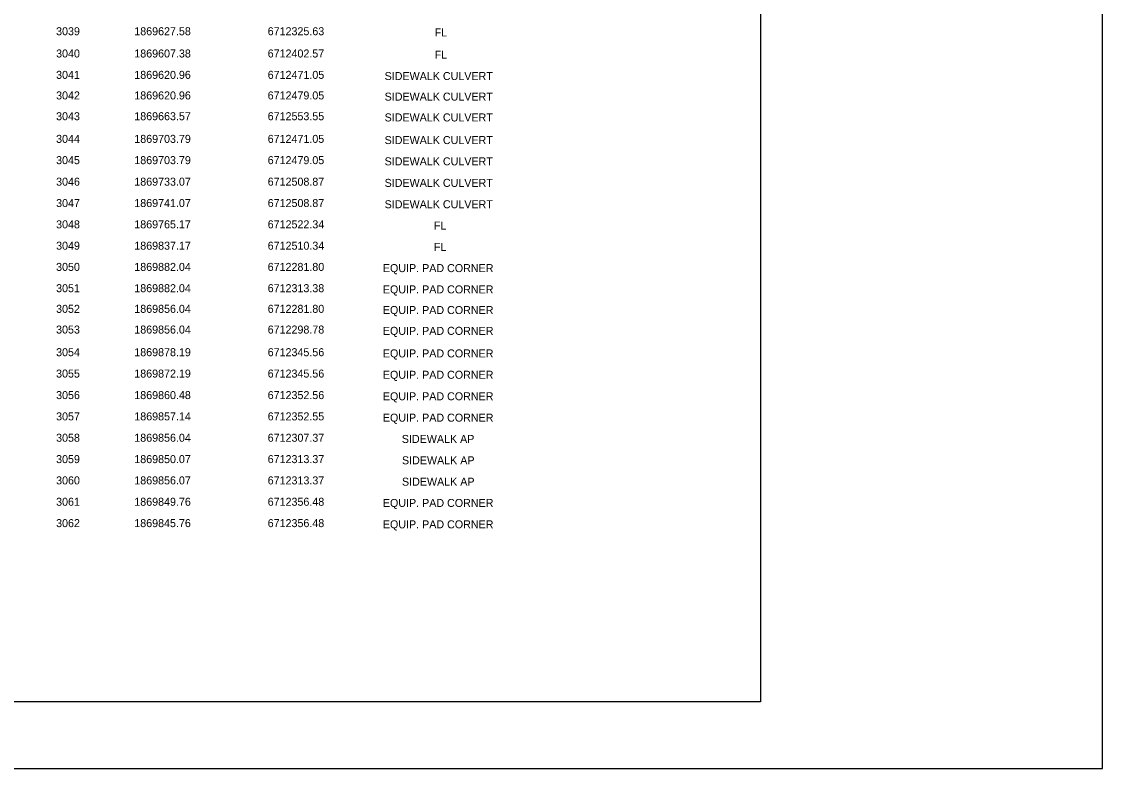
# Model space of a CAD drawing. Extents: x 0 to 4.36, y 0 to 2.5.
# Drawn here: x 2.15 to 3.5, y 0 to 0.933 of the extents above; entities that cross this region are included whole.
import ezdxf

# ---------------------------------------------------------------- set-up
doc = ezdxf.new("R2010")
doc.units = 0
for name, color, linetype in [('C-TEXT', 7, 'Continuous'), ('G-TTLB-OTLN', 7, 'Continuous'), ('G-TTLB-VIEW', 7, 'Continuous')]:
    doc.layers.add(name, color=color, linetype=linetype)

msp = doc.modelspace()

# ---------------------------------------------------------------- linework, layer by layer
at = {"layer": 'G-TTLB-OTLN'}
msp.add_lwpolyline([(0, 0), (3.5, 0), (3.5, 2.5), (0, 2.5)], close=True, dxfattribs=at)
at = {"layer": 'G-TTLB-VIEW'}
msp.add_lwpolyline([(0.1667, 2.4167), (3.0729, 2.4167), (3.0729, 0.0833), (0.1667, 0.0833)], close=True, dxfattribs=at)

# ---------------------------------------------------------------- texts
at = {"layer": 'C-TEXT'}
for s, p in [('3039', (2.1926, 0.9162)), ('1869627.58', (2.2903, 0.9162)), ('6712325.63', (2.457, 0.9162)), ('FL', (2.6656, 0.9147)), ('3040', (2.1926, 0.8884)), ('1869607.38', (2.2903, 0.8884)), ('6712402.57', (2.457, 0.8884)), ('FL', (2.6656, 0.8869)), ('3041', (2.1926, 0.8617)), ('1869620.96', (2.2903, 0.8617)), ('6712471.05', (2.457, 0.8617)), ('SIDEWALK CULVERT', (2.6031, 0.8602)), ('3042', (2.1926, 0.836)), ('1869620.96', (2.2903, 0.836)), ('6712479.05', (2.457, 0.836)), ('SIDEWALK CULVERT', (2.6031, 0.8345)), ('3043', (2.1926, 0.81)), ('1869663.57', (2.2903, 0.81)), ('6712553.55', (2.457, 0.81)), ('SIDEWALK CULVERT', (2.6031, 0.8085)), ('3044', (2.1926, 0.7817)), ('1869703.79', (2.2903, 0.7817)), ('6712471.05', (2.457, 0.7817)), ('SIDEWALK CULVERT', (2.6031, 0.7802)), ('3045', (2.1926, 0.7551)), ('1869703.79', (2.2903, 0.7551)), ('6712479.05', (2.457, 0.7551)), ('SIDEWALK CULVERT', (2.6031, 0.7536)), ('3046', (2.1926, 0.7282)), ('1869733.07', (2.2903, 0.7282)), ('6712508.87', (2.457, 0.7282)), ('SIDEWALK CULVERT', (2.6031, 0.7267)), ('3047', (2.1926, 0.7015)), ('1869741.07', (2.2903, 0.7015)), ('6712508.87', (2.457, 0.7015)), ('SIDEWALK CULVERT', (2.6031, 0.7)), ('3048', (2.1926, 0.6749)), ('1869765.17', (2.2903, 0.6749)), ('6712522.34', (2.457, 0.6749)), ('FL', (2.6647, 0.6733)), ('3049', (2.1926, 0.6482)), ('1869837.17', (2.2903, 0.6482)), ('6712510.34', (2.457, 0.6482)), ('FL', (2.6647, 0.6467)), ('3050', (2.1926, 0.6217)), ('1869882.04', (2.2903, 0.6217)), ('6712281.80', (2.457, 0.6217)), ('EQUIP. PAD CORNER', (2.6009, 0.6202)), ('3051', (2.1926, 0.5951)), ('1869882.04', (2.2903, 0.5951)), ('6712313.38', (2.457, 0.5951)), ('EQUIP. PAD CORNER', (2.6009, 0.5936)), ('3052', (2.1926, 0.5693)), ('1869856.04', (2.2903, 0.5693)), ('6712281.80', (2.457, 0.5693)), ('EQUIP. PAD CORNER', (2.6009, 0.5678)), ('3053', (2.1926, 0.5434)), ('1869856.04', (2.2903, 0.5434)), ('6712298.78', (2.457, 0.5434)), ('EQUIP. PAD CORNER', (2.6009, 0.5418)), ('3054', (2.1926, 0.5151)), ('1869878.19', (2.2903, 0.5151)), ('6712345.56', (2.457, 0.5151)), ('EQUIP. PAD CORNER', (2.6009, 0.5136)), ('3055', (2.1926, 0.4884)), ('1869872.19', (2.2903, 0.4884)), ('6712345.56', (2.457, 0.4884)), ('EQUIP. PAD CORNER', (2.6009, 0.4869)), ('3056', (2.1926, 0.4615)), ('1869860.48', (2.2903, 0.4615)), ('6712352.56', (2.457, 0.4615)), ('EQUIP. PAD CORNER', (2.6009, 0.46)), ('3057', (2.1926, 0.4349)), ('1869857.14', (2.2903, 0.4349)), ('6712352.55', (2.457, 0.4349)), ('EQUIP. PAD CORNER', (2.6009, 0.4333)), ('3058', (2.1926, 0.4082)), ('1869856.04', (2.2903, 0.4082)), ('6712307.37', (2.457, 0.4082)), ('SIDEWALK AP', (2.6246, 0.4067)), ('3059', (2.1926, 0.3815)), ('1869850.07', (2.2903, 0.3815)), ('6712313.37', (2.457, 0.3815)), ('SIDEWALK AP', (2.6248, 0.38)), ('3060', (2.1926, 0.3549)), ('1869856.07', (2.2903, 0.3549)), ('6712313.37', (2.457, 0.3549)), ('SIDEWALK AP', (2.6248, 0.3533)), ('3061', (2.1926, 0.3282)), ('1869849.76', (2.2903, 0.3282)), ('6712356.48', (2.457, 0.3282)), ('EQUIP. PAD CORNER', (2.6009, 0.3267)), ('3062', (2.1926, 0.3015)), ('1869845.76', (2.2903, 0.3015)), ('6712356.48', (2.457, 0.3015)), ('EQUIP. PAD CORNER', (2.6009, 0.3))]:
    msp.add_text(s, height=0.01, dxfattribs=at).set_placement(p)

doc.saveas('drawing.dxf')
